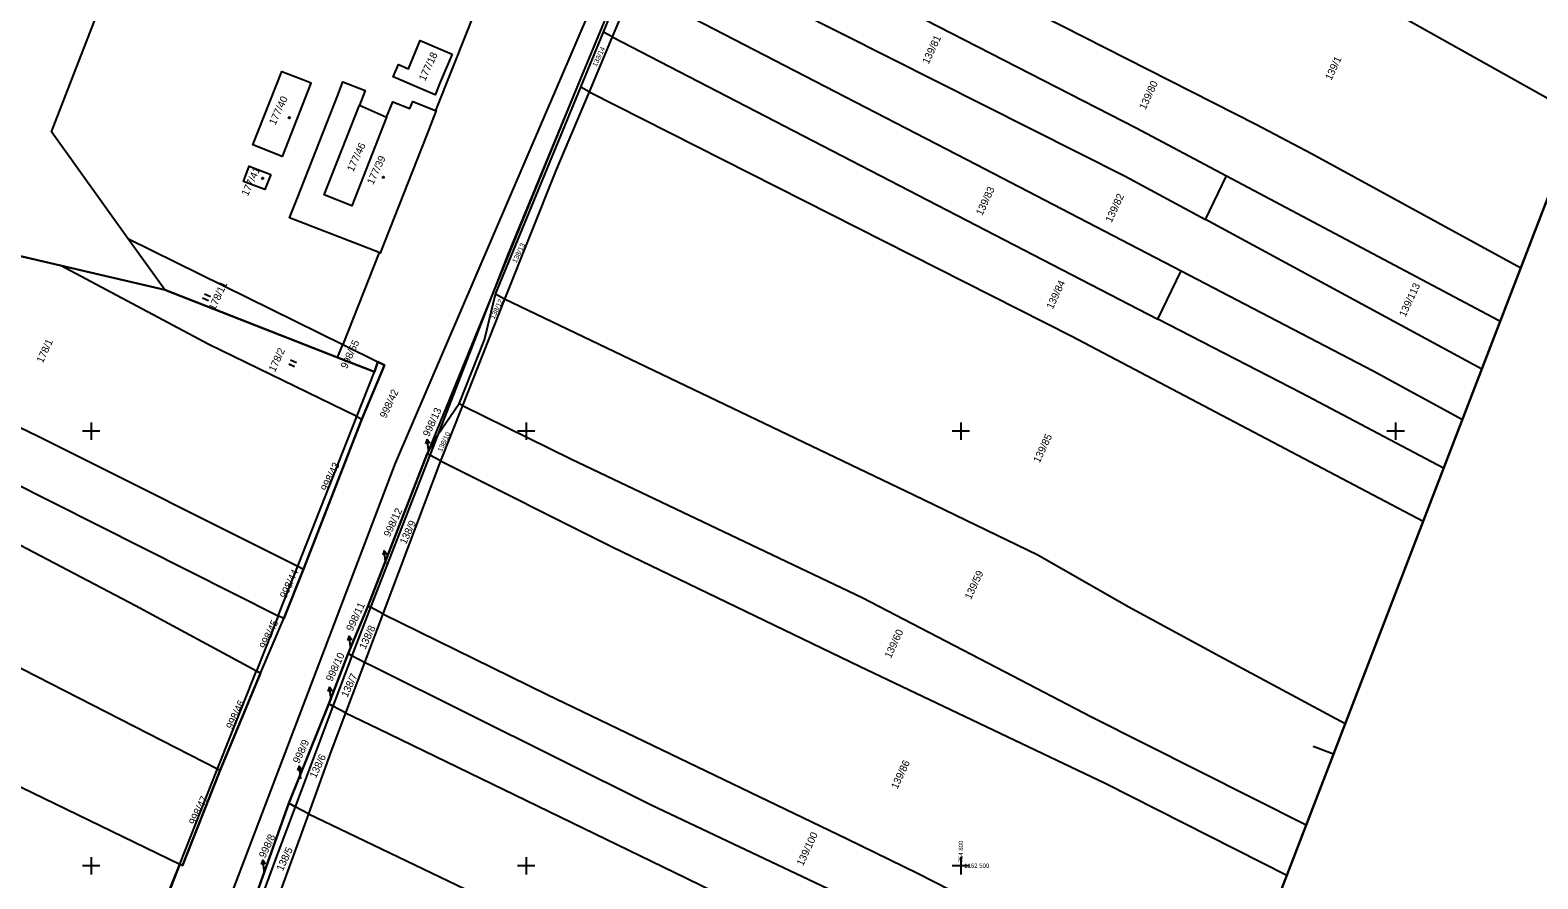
# Model space of a CAD drawing. Extents: x -755344 to -754412, y -1162670 to -1161477.
# Drawn here: x -755014.1 to -754667.3, y -1162503 to -1162307.8 of the extents above; entities that cross this region are included whole.
import ezdxf

# ---------------------------------------------------------------- set-up
doc = ezdxf.new("R2010")
doc.units = 0
for name, color, linetype in [('Formát', 7, 'Continuous'), ('Katastrální hranice', 7, 'Continuous'), ('Síť', 7, 'Continuous'), ('Vrstva 53', 7, 'Continuous'), ('Vrstva 55', 7, 'Continuous'), ('Vrstva 57', 7, 'Continuous'), ('Vrstva 58', 7, 'Continuous'), ('Vrstva 59', 7, 'Continuous')]:
    doc.layers.add(name, color=color, linetype=linetype)

msp = doc.modelspace()

# ---------------------------------------------------------------- linework, layer by layer
at = {"layer": 'Formát'}
msp.add_line((-754714.29, -1162474.33), (-754718.95, -1162472.54), dxfattribs=at)
msp.add_lwpolyline([(-754488.01, -1161886.37), (-754789.71, -1162670.32), (-755344.08, -1162456.97), (-755042.37, -1161673.02)], close=True, dxfattribs=at)
for points in [[(-755344.08, -1162456.97), (-754789.71, -1162670.32), (-754488.01, -1161886.37), (-755042.37, -1161673.02)], [(-755344.08, -1162456.97), (-754789.71, -1162670.32), (-754488.01, -1161886.37), (-755042.37, -1161673.02)], [(-754789.71, -1162670.32), (-754488.01, -1161886.37), (-755042.37, -1161673.02), (-755344.08, -1162456.97)]]:
    msp.add_lwpolyline(points, dxfattribs=at)
at = {"layer": 'Katastrální hranice'}
for p, q in [((-754904.19, -1162359.38), (-754920.39, -1162401.05)), ((-754920.39, -1162401.05), (-754922.13, -1162405.53)), ((-754922.13, -1162405.53), (-754935.75, -1162440.55)), ((-754940.08, -1162451.73), (-754944.44, -1162463.31)), ((-754944.44, -1162463.31), (-754953.13, -1162486.42))]:
    msp.add_line(p, q, dxfattribs=at)
for points in [[(-754816.22, -1162147.35), (-754851.45, -1162231.96), (-754887.61, -1162319.28), (-754904.19, -1162359.38)], [(-754935.75, -1162440.55), (-754939.77, -1162450.9), (-754940.08, -1162451.73)], [(-754953.13, -1162486.42), (-754957.12, -1162497.02), (-754961.39, -1162508.73)]]:
    msp.add_lwpolyline(points, dxfattribs=at)
at = {"layer": 'Síť'}
for points in [[(-755000, -1162398), (-755000, -1162400), (-755000, -1162402)], [(-754900, -1162398), (-754900, -1162400), (-754900, -1162402)], [(-754800, -1162398), (-754800, -1162400), (-754800, -1162402)], [(-754700, -1162398), (-754700, -1162400), (-754700, -1162402)], [(-754998, -1162400), (-755000, -1162400), (-755002, -1162400)], [(-754898, -1162400), (-754900, -1162400), (-754902, -1162400)], [(-754798, -1162400), (-754800, -1162400), (-754802, -1162400)], [(-754698, -1162400), (-754700, -1162400), (-754702, -1162400)], [(-755000, -1162498), (-755000, -1162500), (-755000, -1162502)], [(-754900, -1162498), (-754900, -1162500), (-754900, -1162502)], [(-754800, -1162498), (-754800, -1162500), (-754800, -1162502)], [(-754998, -1162500), (-755000, -1162500), (-755002, -1162500)], [(-754898, -1162500), (-754900, -1162500), (-754902, -1162500)], [(-754798, -1162500), (-754800, -1162500), (-754802, -1162500)]]:
    msp.add_lwpolyline(points, dxfattribs=at)
at = {"layer": 'Vrstva 53'}
for points in [[(-754851.45, -1162231.96), (-754887.61, -1162319.28), (-754922.76, -1162405.23), (-754936.37, -1162440.35), (-754940.94, -1162451.2), (-754945.37, -1162462.72), (-754954.58, -1162485.64), (-754962.59, -1162508.22)], [(-754988.9, -1162522.63), (-754979.63, -1162499.65), (-754979.01, -1162499.95), (-754970.36, -1162478), (-754961.09, -1162455.7), (-754955.75, -1162443.15), (-754951.16, -1162431.76), (-754937.81, -1162397.22), (-754932.57, -1162384.85), (-754934.1, -1162384.09), (-754934.85, -1162386.36), (-754943.35, -1162383.04), (-754983.11, -1162367.53), (-755007.12, -1162361.91), (-755096.49, -1162341)]]:
    msp.add_lwpolyline(points, dxfattribs=at)
at = {"layer": 'Vrstva 55'}
for p, q in [((-754882.21, -1162308.21), (-754877.36, -1162296.41)), ((-754887.42, -1162320.88), (-754882.21, -1162308.21)), ((-754880.18, -1162309.28), (-754885.52, -1162321.91)), ((-754880.18, -1162309.28), (-754882.21, -1162308.21)), ((-754880.18, -1162309.28), (-754754.66, -1162374.22)), ((-754907, -1162368.52), (-754887.42, -1162320.88)), ((-754885.52, -1162321.91), (-754887.42, -1162320.88)), ((-754938.35, -1162324.98), (-754932.08, -1162327.81)), ((-755096.49, -1162341), (-755007.12, -1162361.91)), ((-754743.7, -1162351.33), (-754738.88, -1162341.27)), ((-754983.11, -1162367.53), (-754991.59, -1162355.66)), ((-754991.59, -1162355.66), (-754942.18, -1162380.1)), ((-754933.79, -1162358.94), (-754942.18, -1162380.1)), ((-754904.19, -1162359.38), (-754920.39, -1162401.05)), ((-754904.19, -1162359.38), (-754920.39, -1162401.05)), ((-755007.12, -1162361.91), (-754983.11, -1162367.53)), ((-754754.66, -1162374.22), (-754749.36, -1162363.14)), ((-754983.11, -1162367.53), (-754943.35, -1162383.04)), ((-754904.94, -1162369.67), (-754914.65, -1162394.09)), ((-754904.94, -1162369.67), (-754907, -1162368.52)), ((-754943.35, -1162383.04), (-754942.18, -1162380.1)), ((-754942.18, -1162380.1), (-754934.1, -1162384.09)), ((-754943.35, -1162383.04), (-754934.85, -1162386.36)), ((-754934.85, -1162386.36), (-754934.1, -1162384.09)), ((-754938.92, -1162396.68), (-754934.85, -1162386.36)), ((-754915.36, -1162393.71), (-754920.39, -1162401.05)), ((-754914.65, -1162394.09), (-754919.68, -1162406.81)), ((-754914.65, -1162394.09), (-754915.36, -1162393.71)), ((-754952.51, -1162431.09), (-754938.92, -1162396.68)), ((-754937.81, -1162397.22), (-754951.16, -1162431.76)), ((-754938.92, -1162396.68), (-754937.81, -1162397.22)), ((-754922.76, -1162405.23), (-754920.39, -1162401.05)), ((-754920.39, -1162401.05), (-754922.13, -1162405.53)), ((-754920.39, -1162401.05), (-754922.13, -1162405.53)), ((-754936.37, -1162440.35), (-754922.76, -1162405.23)), ((-754922.13, -1162405.53), (-754935.75, -1162440.55)), ((-754922.13, -1162405.53), (-754935.75, -1162440.55)), ((-754919.68, -1162406.81), (-754932.95, -1162442.03)), ((-754922.13, -1162405.53), (-754922.76, -1162405.23)), ((-754919.68, -1162406.81), (-754922.13, -1162405.53)), ((-754957.02, -1162442.51), (-754952.51, -1162431.09)), ((-754951.16, -1162431.76), (-754955.75, -1162443.15)), ((-754952.51, -1162431.09), (-754951.16, -1162431.76)), ((-754961.09, -1162455.7), (-754955.75, -1162443.15)), ((-754955.75, -1162443.15), (-754957.02, -1162442.51)), ((-754940.94, -1162451.2), (-754936.37, -1162440.35)), ((-754932.95, -1162442.03), (-754937.16, -1162453.22)), ((-754935.75, -1162440.55), (-754936.37, -1162440.35)), ((-754932.95, -1162442.03), (-754935.75, -1162440.55)), ((-754945.37, -1162462.72), (-754940.94, -1162451.2)), ((-754940.08, -1162451.73), (-754944.44, -1162463.31)), ((-754940.08, -1162451.73), (-754944.44, -1162463.31)), ((-754937.16, -1162453.22), (-754941.53, -1162464.82)), ((-754940.08, -1162451.73), (-754940.94, -1162451.2)), ((-754937.16, -1162453.22), (-754940.08, -1162451.73)), ((-754970.94, -1162477.7), (-754962.03, -1162455.19)), ((-754961.09, -1162455.7), (-754970.36, -1162478)), ((-754962.03, -1162455.19), (-754961.09, -1162455.7)), ((-754954.58, -1162485.64), (-754945.37, -1162462.72)), ((-754944.44, -1162463.31), (-754953.13, -1162486.42)), ((-754944.44, -1162463.31), (-754953.13, -1162486.42)), ((-754944.44, -1162463.31), (-754945.37, -1162462.72)), ((-754941.53, -1162464.82), (-754944.44, -1162463.31)), ((-754979.63, -1162499.65), (-754970.94, -1162477.7)), ((-754970.94, -1162477.7), (-754970.36, -1162478)), ((-754962.59, -1162508.22), (-754954.58, -1162485.64)), ((-754950.07, -1162488.05), (-754958.17, -1162510.4)), ((-754953.13, -1162486.42), (-754954.58, -1162485.64)), ((-754950.07, -1162488.05), (-754953.13, -1162486.42))]:
    msp.add_line(p, q, dxfattribs=at)
for points in [[(-754978.01, -1162551.88), (-754981.37, -1162542.41), (-754930.02, -1162407.36), (-754870.17, -1162267.96), (-754836.4, -1162183.6), (-754824.89, -1162157.4), (-754808.97, -1162117.64), (-754790.52, -1162068.93), (-754761.32, -1161999.17), (-754754.27, -1161988.55)], [(-754816.22, -1162147.35), (-754851.45, -1162231.96), (-754887.61, -1162319.28), (-754904.19, -1162359.38)], [(-754816.22, -1162147.35), (-754851.45, -1162231.96), (-754887.61, -1162319.28), (-754904.19, -1162359.38)], [(-754878.41, -1162219.27), (-754890.63, -1162250.1), (-754895.21, -1162261.65), (-754899.8, -1162273.21), (-754904.37, -1162284.73), (-754908.92, -1162296.21), (-754913.49, -1162307.74), (-754920.81, -1162326.21)], [(-754657.78, -1162327.52), (-754706.68, -1162300.09), (-754748.68, -1162279.47), (-754846.58, -1162228.99)], [(-754861.29, -1162263.76), (-754731.98, -1162329.45), (-754719.33, -1162336.16), (-754671.23, -1162362.45)], [(-754866.17, -1162275.57), (-754759.65, -1162330.23), (-754738.88, -1162341.27)], [(-754991.59, -1162355.66), (-755009.14, -1162331.11), (-755004.94, -1162320.25), (-754995.6, -1162296.07), (-754989.19, -1162279.49)], [(-754870.74, -1162286.62), (-754762.18, -1162341.31), (-754743.7, -1162351.33)], [(-754875.34, -1162297.75), (-754877.03, -1162301.83), (-754880.18, -1162309.28)], [(-754875.34, -1162297.75), (-754796.43, -1162338.66), (-754749.36, -1162363.14)], [(-754917, -1162313.28), (-754919.73, -1162319.74), (-754920.94, -1162322.61), (-754922.89, -1162321.82), (-754930.54, -1162318.52), (-754929.32, -1162315.68), (-754927.01, -1162316.65), (-754924.39, -1162310.17), (-754917, -1162313.28)], [(-754949.46, -1162319.85), (-754949.5, -1162319.95), (-754956.1, -1162336.8), (-754962.81, -1162334.17), (-754956.15, -1162317.23), (-754951.35, -1162319.11), (-754949.46, -1162319.85)], [(-754933.79, -1162358.94), (-754954.4, -1162350.9), (-754952.59, -1162346.32), (-754943.32, -1162322.74), (-754942.11, -1162319.68), (-754937.04, -1162321.65), (-754938.35, -1162324.98)], [(-754932.08, -1162327.81), (-754940.04, -1162348.18), (-754946.47, -1162345.65), (-754938.35, -1162324.98)], [(-754932.08, -1162327.81), (-754930.68, -1162324.22), (-754926.7, -1162325.77), (-754926.07, -1162324.16), (-754920.81, -1162326.21)], [(-754885.52, -1162321.91), (-754893.18, -1162340.03), (-754904.94, -1162369.67)], [(-754885.52, -1162321.91), (-754774.5, -1162378.17), (-754693.66, -1162420.73)], [(-754920.81, -1162326.21), (-754920.65, -1162326.27), (-754922.89, -1162331.96), (-754932.49, -1162356.33), (-754933.56, -1162359.03), (-754933.79, -1162358.94)], [(-754958.7, -1162341), (-754959.46, -1162342.9), (-754960.08, -1162344.45), (-754965.03, -1162342.55), (-754964.25, -1162340.51), (-754963.68, -1162339.01), (-754958.7, -1162341)], [(-754738.88, -1162341.27), (-754676.48, -1162374.42), (-754675.94, -1162374.7)], [(-754680.2, -1162385.77), (-754743.7, -1162351.33)], [(-755099.55, -1162362.44), (-755065.93, -1162375.26), (-755012.09, -1162401.26), (-754952.51, -1162431.09)], [(-754938.92, -1162396.68), (-754972.93, -1162380.07), (-755007.12, -1162361.91)], [(-754749.36, -1162363.14), (-754705.16, -1162386.13), (-754684.64, -1162397.31)], [(-754915.36, -1162393.71), (-754909.53, -1162379), (-754907, -1162368.52)], [(-754711.6, -1162467.36), (-754740.47, -1162451.9), (-754761.55, -1162440.45), (-754782.29, -1162428.56), (-754810.81, -1162414.71), (-754904.94, -1162369.67)], [(-755101.09, -1162374.25), (-755066.17, -1162388.99), (-755029.41, -1162406.11), (-754957.02, -1162442.51)], [(-754688.97, -1162408.54), (-754721.69, -1162391.28), (-754754.66, -1162374.22)], [(-754934.1, -1162384.09), (-754932.57, -1162384.85), (-754937.81, -1162397.22)], [(-755102.66, -1162386.37), (-755046.04, -1162410.7), (-754989.82, -1162440.1), (-754962.03, -1162455.19)], [(-754914.65, -1162394.09), (-754889.54, -1162406.43), (-754822.7, -1162438.27), (-754789.93, -1162455.34), (-754769.94, -1162465.78), (-754720.55, -1162490.61)], [(-754919.68, -1162406.81), (-754880.07, -1162426.68), (-754823.32, -1162454.05), (-754766.65, -1162481.08), (-754725.01, -1162502.2)], [(-755108.76, -1162411.24), (-755073.63, -1162426.1), (-755047.73, -1162438.47), (-754970.94, -1162477.7)], [(-755102.04, -1162441.81), (-755081.44, -1162450.28), (-754979.63, -1162499.65)], [(-754957.02, -1162442.51), (-754958.5, -1162446.27), (-754962.03, -1162455.19)], [(-754935.75, -1162440.55), (-754939.77, -1162450.9), (-754940.08, -1162451.73)], [(-754935.75, -1162440.55), (-754939.77, -1162450.9), (-754940.08, -1162451.73)], [(-754932.95, -1162442.03), (-754895.12, -1162460.64), (-754826.15, -1162493.85), (-754809.95, -1162501.75), (-754768.98, -1162522.66), (-754738.59, -1162537.48)], [(-754743.11, -1162549.24), (-754752.28, -1162544.32), (-754830.58, -1162505.29), (-754871.24, -1162486.05), (-754935.11, -1162454.22), (-754937.16, -1162453.22)], [(-754941.53, -1162464.82), (-754944.83, -1162473.57), (-754950.07, -1162488.05)], [(-754941.53, -1162464.82), (-754934.04, -1162468.42), (-754863.22, -1162502.76), (-754838.48, -1162514.89), (-754806.14, -1162530.97), (-754747.37, -1162560.3)], [(-754970.36, -1162478), (-754979.01, -1162499.95), (-754979.63, -1162499.65)], [(-754953.13, -1162486.42), (-754957.12, -1162497.02), (-754961.39, -1162508.73)], [(-754953.13, -1162486.42), (-754957.12, -1162497.02), (-754961.39, -1162508.73)], [(-754950.07, -1162488.05), (-754944.78, -1162490.56), (-754893.03, -1162515.45), (-754858.48, -1162531.49), (-754830.45, -1162545.87), (-754756.13, -1162583.06)], [(-754979.63, -1162499.65), (-754983.12, -1162508.48), (-754988.9, -1162522.63)]]:
    msp.add_lwpolyline(points, dxfattribs=at)
at = {"layer": 'Vrstva 57'}
for p, q in [((-754922.75, -1162401.87), (-754923.12, -1162402.93)), ((-754922.36, -1162404.85), (-754922.75, -1162401.87)), ((-754922.75, -1162401.87), (-754922.13, -1162402.8)), ((-754932.61, -1162427.47), (-754932.97, -1162428.53)), ((-754932.22, -1162430.45), (-754932.61, -1162427.47)), ((-754932.61, -1162427.47), (-754931.98, -1162428.4)), ((-754940.71, -1162447.12), (-754941.08, -1162448.18)), ((-754940.32, -1162450.1), (-754940.71, -1162447.12)), ((-754940.71, -1162447.12), (-754940.09, -1162448.05)), ((-754945.23, -1162458.86), (-754945.6, -1162459.91)), ((-754944.84, -1162461.83), (-754945.23, -1162458.86)), ((-754945.23, -1162458.86), (-754944.6, -1162459.79)), ((-754952.22, -1162477.03), (-754952.59, -1162478.09)), ((-754951.84, -1162480.01), (-754952.22, -1162477.03)), ((-754952.22, -1162477.03), (-754951.6, -1162477.96)), ((-754960.55, -1162498.66), (-754960.91, -1162499.71)), ((-754960.16, -1162501.63), (-754960.55, -1162498.66)), ((-754960.55, -1162498.66), (-754959.92, -1162499.58))]:
    msp.add_line(p, q, dxfattribs=at)
at = {"layer": 'Vrstva 58'}
for p, q in [((-754973.04, -1162370.03), (-754974.4, -1162369.4)), ((-754972.61, -1162369.13), (-754973.97, -1162368.49)), ((-754952.82, -1162384.3), (-754954.18, -1162383.67)), ((-754953.24, -1162385.21), (-754954.6, -1162384.57))]:
    msp.add_line(p, q, dxfattribs=at)
at = {"layer": 'Vrstva 59'}
for centre in [(-754954.47, -1162327.88), (-754960.57, -1162341.83), (-754932.82, -1162341.59)]:
    msp.add_circle(centre, 0.175, dxfattribs=at)

# ---------------------------------------------------------------- texts
at = {"layer": 'Síť'}
for s, rotation, p in [('  754 800', 90, (-754799.5, -1162500)), ('  1162 500', 360, (-754800, -1162500.5))]:
    msp.add_text(s, height=1, rotation=rotation, dxfattribs=at).set_placement(p)
at = {"layer": 'Vrstva 57'}
for s, height, p in [('139/81', 1.7, (-754807.43, -1162315.72)), ('177/18', 1.7, (-754923.24, -1162319.62)), ('138/14', 1.139, (-754883.8, -1162316.27)), ('139/1', 1.7, (-754714.79, -1162319.43)), ('139/80', 1.7, (-754757.56, -1162326.2)), ('177/40', 1.7, (-754957.69, -1162329.74)), ('177/46', 1.7, (-754939.76, -1162340.49)), ('177/39', 1.7, (-754935.17, -1162343.44)), ('177/41', 1.7, (-754964.02, -1162346.07)), ('139/83', 1.7, (-754795.1, -1162350.56)), ('139/82', 1.7, (-754765.34, -1162352.16)), ('138/13', 1.139, (-754902.23, -1162361.44)), ('178/11', 1.7, (-754971.58, -1162372.35)), ('139/84', 1.7, (-754778.88, -1162372.1)), ('139/113', 1.7, (-754697.77, -1162373.87)), ('138/12', 1.139, (-754907.29, -1162374.33)), ('178/1', 1.7, (-755011.16, -1162384.48)), ('998/55', 1.7, (-754941.22, -1162385.81)), ('178/2', 1.7, (-754957.77, -1162386.53)), ('998/42', 1.7, (-754932.22, -1162397.19)), ('998/13', 1.7, (-754922.32, -1162401.43)), ('138/10', 1.139, (-754919.4, -1162404.89)), ('139/85', 1.7, (-754781.89, -1162407.46)), ('998/43', 1.7, (-754945.75, -1162413.99)), ('998/12', 1.7, (-754931.34, -1162424.52)), ('138/9', 1.7, (-754927.63, -1162426.21)), ('998/44', 1.7, (-754955.21, -1162438.64)), ('139/59', 1.7, (-754797.68, -1162438.88)), ('998/11', 1.7, (-754939.94, -1162446.21)), ('998/45', 1.7, (-754959.88, -1162450.25)), ('138/8', 1.7, (-754936.97, -1162450.36)), ('139/60', 1.7, (-754816.11, -1162452.42)), ('998/10', 1.7, (-754944.62, -1162457.76)), ('138/7', 1.7, (-754941.11, -1162461.41)), ('998/46', 1.7, (-754967.56, -1162468.73)), ('998/9', 1.7, (-754952.21, -1162476.63)), ('138/6', 1.7, (-754948.35, -1162480.01)), ('139/86', 1.7, (-754814.61, -1162482.52)), ('998/47', 1.7, (-754976.11, -1162490.75)), ('998/8', 1.7, (-754960.01, -1162498.39)), ('139/100', 1.7, (-754836.32, -1162500.2)), ('138/5', 1.7, (-754955.98, -1162501.38))]:
    msp.add_text(s, height=height, rotation=65, dxfattribs=at).set_placement(p)

doc.saveas('drawing.dxf')
